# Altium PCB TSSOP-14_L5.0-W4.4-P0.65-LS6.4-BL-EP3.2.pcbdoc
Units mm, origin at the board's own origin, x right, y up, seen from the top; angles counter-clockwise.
Board outline 18 x 20.18 mm, 2 copper layers (Top Layer, Bottom Layer), stack 0 mm thick; 1 components, 0 nets, 15 pads, 0 vias.
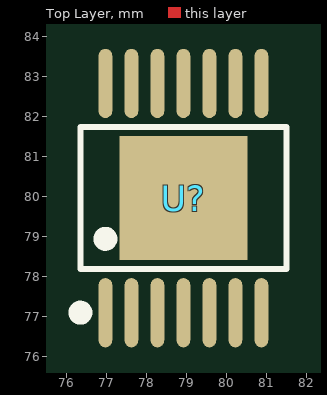
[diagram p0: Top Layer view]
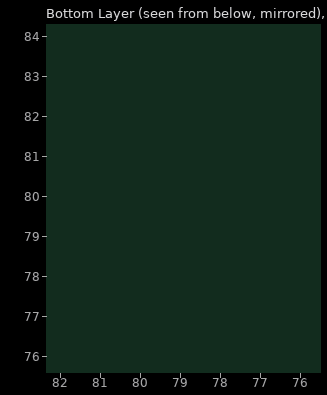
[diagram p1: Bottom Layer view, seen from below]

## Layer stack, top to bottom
Top Layer: signal copper (thickness not stored)
Bottom Layer: signal copper (thickness not stored)

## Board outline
87.85,69.85 69.85,69.85 69.85,90.031 87.85,90.031

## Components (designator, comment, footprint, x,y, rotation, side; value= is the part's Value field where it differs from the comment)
U? "" TSSOP-14_L5.0-W4.4-P0.65-LS6.4-BL-EP3.2 78.924,79.95 r0 top

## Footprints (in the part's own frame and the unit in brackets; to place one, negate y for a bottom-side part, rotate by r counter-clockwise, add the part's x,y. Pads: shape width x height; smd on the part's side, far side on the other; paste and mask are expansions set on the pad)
TSSOP-14_L5.0-W4.4-P0.65-LS6.4-BL-EP3.2 [mm]
  oval 0.343x1.731 smd: 1(-1.95,-2.866) 2(-1.3,-2.866) 3(-0.65,-2.866) 4(0,-2.866) 5(0.65,-2.866) 6(1.3,-2.866) 7(1.95,-2.866) 8(1.95,2.866) 9(1.3,2.866) 10(0.65,2.866) 11(0,2.866) 12(-0.65,2.866) 13(-1.3,2.866) 14(-1.95,2.866)
  rect 3.2x3.1 smd: 15(0,0)
  silkscreen extent -2.72,-3.02 2.58,1.77

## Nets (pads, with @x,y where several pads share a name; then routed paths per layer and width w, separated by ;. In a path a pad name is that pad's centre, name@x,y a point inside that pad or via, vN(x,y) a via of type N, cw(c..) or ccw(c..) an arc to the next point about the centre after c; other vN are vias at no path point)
pads on no net: U?.1 U?.2 U?.3 U?.4 U?.5 U?.6 U?.7 U?.8 U?.9 U?.10 U?.11 U?.12 U?.13 U?.14 U?.15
